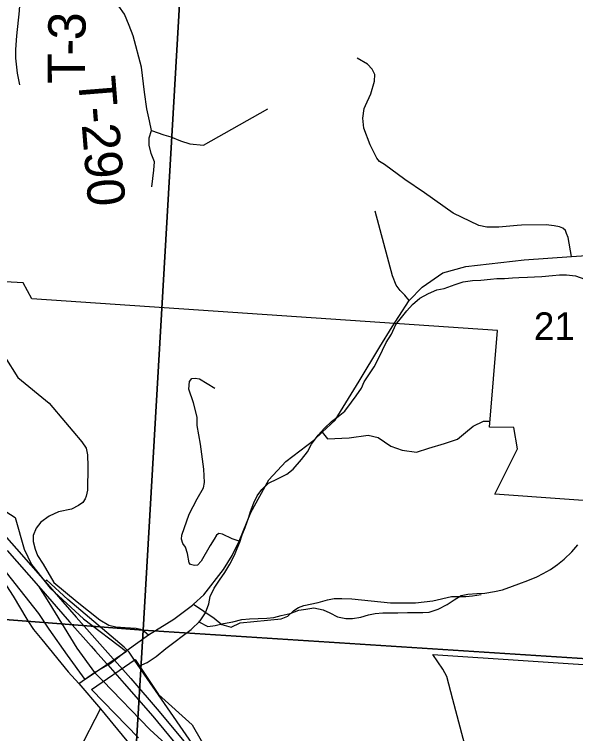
# Model space of a CAD drawing. Extents: x 0 to 34, y 0 to 22.
# Drawn here: x 3.35 to 4.203, y 15.269 to 16.363 of the extents above; entities that cross this region are included whole.
import ezdxf

# ---------------------------------------------------------------- set-up
doc = ezdxf.new("R2010")
doc.units = 0
for name, color, linetype in [('GM_X_City_Street', 7, 'Continuous'), ('GM_X_Corporation', 7, 'Continuous'), ('GM_X_Interchange_Ramps', 7, 'Continuous'), ('GM_X_Minor_River', 7, 'Continuous'), ('GM_X_Section_Text', 7, 'Continuous'), ('GM_X_State_Route', 7, 'Continuous'), ('GM_X_Township_Road', 7, 'Continuous'), ('GM_X_Township_Road_Text', 7, 'Continuous'), ('GM_X_US_Route', 7, 'Continuous')]:
    doc.layers.add(name, color=color, linetype=linetype)

msp = doc.modelspace()

# ---------------------------------------------------------------- linework, layer by layer
at = {"layer": 'GM_X_City_Street'}
for p, q in [((3.4478, 15.3456), (3.4715, 15.3624)), ((3.4355, 15.2191), (3.4806, 15.3072))]:
    msp.add_line(p, q, dxfattribs=at)
for points in [[(3.3351, 15.8422), (3.355, 15.8107), (3.4028, 15.7721), (3.4276, 15.7427), (3.4388, 15.7295)], [(3.6917, 15.5618), (3.6808, 15.5658), (3.6661, 15.5729), (3.6605, 15.5736), (3.657, 15.5709), (3.6534, 15.5649), (3.6476, 15.5556), (3.634, 15.5317), (3.6282, 15.5257), (3.6235, 15.5252), (3.6177, 15.5266), (3.6155, 15.5292), (3.6128, 15.5431), (3.6101, 15.5531), (3.6061, 15.5587), (3.6039, 15.5649), (3.6046, 15.5709), (3.6156, 15.6031), (3.6275, 15.6263), (3.6372, 15.6432), (3.639, 15.6513), (3.6377, 15.6716), (3.633, 15.7094), (3.6277, 15.7378), (3.6278, 15.7507), (3.6222, 15.7724), (3.6151, 15.7933), (3.6163, 15.8047), (3.6197, 15.8093), (3.6246, 15.81), (3.6311, 15.8088), (3.6545, 15.7947)], [(3.8178, 15.7276), (3.8261, 15.7176), (3.8587, 15.7194), (3.8876, 15.7234), (3.9027, 15.7195), (3.9224, 15.7065), (3.9394, 15.7004), (3.9614, 15.6973), (3.98, 15.7032), (4.0036, 15.7107), (4.0234, 15.7171), (4.0359, 15.7273), (4.0474, 15.7368), (4.0629, 15.7447), (4.0732, 15.7444)], [(3.4388, 15.7295), (3.4526, 15.7133), (3.4588, 15.7034), (3.4612, 15.6932), (3.4614, 15.6758), (3.4612, 15.6398), (3.4588, 15.6302), (3.4575, 15.6263), (3.4537, 15.6206), (3.4471, 15.6164), (3.4365, 15.6109), (3.417, 15.6065), (3.4028, 15.5998), (3.39, 15.5907), (3.383, 15.5816), (3.3786, 15.5708), (3.3783, 15.5617), (3.3813, 15.55), (3.3848, 15.5402), (3.3935, 15.5269), (3.4096, 15.4991), (3.4453, 15.4698), (3.4799, 15.4425), (3.4933, 15.4344), (3.5041, 15.4316), (3.5184, 15.4306), (3.5348, 15.4295), (3.5415, 15.4281), (3.547, 15.425), (3.554, 15.4194)], [(3.3114, 15.5339), (3.3479, 15.4786), (3.369, 15.4436)], [(3.622, 15.466), (3.6534, 15.4448), (3.6653, 15.4354), (3.6795, 15.4313), (3.6929, 15.4377), (3.7552, 15.444), (3.7654, 15.4481), (3.7746, 15.4565), (3.7817, 15.461), (3.7901, 15.4644), (3.8115, 15.4689), (3.8259, 15.4726), (3.8358, 15.4749), (3.8476, 15.4749), (3.863, 15.4741), (3.9215, 15.468), (3.9596, 15.468), (3.9862, 15.4714), (4.0142, 15.4778), (4.0361, 15.4781), (4.0461, 15.4789), (4.0594, 15.4807)], [(3.369, 15.4436), (3.3705, 15.4411), (3.3791, 15.4277), (3.3915, 15.4126), (3.4318, 15.3635), (3.4478, 15.3456)], [(3.4478, 15.3456), (3.4806, 15.3072), (3.5394, 15.2355), (3.5828, 15.1854), (3.5875, 15.1791), (3.6236, 15.1439), (3.6441, 15.1243), (3.6603, 15.1084), (3.6672, 15.0977), (3.6737, 15.0882), (3.7088, 15.0315), (3.776, 14.9293), (3.8503, 14.8112), (3.8974, 14.7371), (3.9444, 14.6625), (4.038, 14.514), (4.0485, 14.5009)]]:
    msp.add_lwpolyline(points, dxfattribs=at)
at = {"layer": 'GM_X_Corporation'}
for points in [[(3.6056, 16.4577), (3.5455, 15.4266), (2.5724, 15.5017), (2.6188, 16.52)], [(4.6087, 16.3871), (4.5353, 15.3628), (3.5455, 15.4266), (3.6056, 16.4577)], [(3.5455, 15.4266), (4.5353, 15.3628), (4.4813, 14.3453), (3.4851, 14.4189)]]:
    msp.add_lwpolyline(points, close=True, dxfattribs=at)
for points in [[(4.2921, 15.6181), (4.0804, 15.6335), (4.1149, 15.7024), (4.1093, 15.7347), (4.0722, 15.7353), (4.0842, 15.8825), (3.3765, 15.9305), (3.3633, 15.9548), (3.2992, 15.9585)], [(3.2977, 15.6319), (3.351, 15.5979), (3.3648, 15.55), (3.3757, 15.5264), (3.4044, 15.4906), (3.455, 15.4437), (3.5201, 15.3944), (3.4573, 15.3518), (3.4305, 15.3887), (3.4026, 15.4283), (3.3868, 15.4519), (3.3377, 15.5144)], [(2.6377, 15.2265), (2.6117, 15.2766), (2.597, 15.3031), (2.5781, 15.3392), (2.5705, 15.3517), (2.5668, 15.3574), (2.5528, 15.3783), (2.5294, 15.4116), (2.5203, 15.4333), (2.5199, 15.442), (2.5222, 15.4507), (2.5268, 15.4556), (2.5715, 15.4744), (2.5724, 15.5017), (3.5455, 15.4266), (3.4851, 14.4189)], [(4.0369, 15.2448), (4.0164, 15.3212), (4.0071, 15.3562), (4.001, 15.3676), (3.986, 15.3897), (4.2757, 15.3706)], [(3.5388, 15.2629), (3.4671, 15.3365), (3.5337, 15.3822), (3.5691, 15.3289), (3.6201, 15.2827), (3.6476, 15.2351)]]:
    msp.add_lwpolyline(points, dxfattribs=at)
at = {"layer": 'GM_X_Interchange_Ramps'}
for p, q in [((3.5518, 15.3532), (3.5327, 15.3809)), ((3.5691, 15.3282), (3.5518, 15.3532))]:
    msp.add_line(p, q, dxfattribs=at)
for points in [[(3.5214, 15.3965), (3.5169, 15.401), (3.4312, 15.4731), (3.3992, 15.5027), (3.3965, 15.5008)], [(3.5327, 15.3809), (3.5243, 15.393), (3.5214, 15.3965)], [(3.4715, 15.3624), (3.4759, 15.3583), (3.4842, 15.3497)], [(3.4842, 15.3497), (3.556, 15.2756), (3.6043, 15.231), (3.6211, 15.2145), (3.625, 15.2177)], [(3.6275, 15.2334), (3.6321, 15.2365), (3.6247, 15.2478), (3.5691, 15.3282)]]:
    msp.add_lwpolyline(points, dxfattribs=at)
at = {"layer": 'GM_X_Minor_River'}
for points in [[(3.539, 15.3721), (3.5519, 15.3777), (3.5655, 15.3869), (3.5803, 15.399), (3.5942, 15.4096), (3.6048, 15.4176), (3.6188, 15.4275), (3.6324, 15.4407), (3.6404, 15.4529), (3.6453, 15.4665), (3.6476, 15.4779), (3.6536, 15.4904), (3.6615, 15.5026), (3.6699, 15.5143), (3.6774, 15.5272), (3.6846, 15.5405), (3.6888, 15.5507), (3.6926, 15.5606), (3.6963, 15.5716), (3.7009, 15.583), (3.7058, 15.597), (3.7088, 15.6069), (3.7137, 15.6205), (3.719, 15.6311), (3.7262, 15.6406), (3.7364, 15.6501), (3.75, 15.6569), (3.764, 15.6638), (3.7738, 15.6717), (3.7863, 15.6861), (3.7954, 15.6979), (3.8015, 15.7097), (3.8117, 15.7233), (3.8211, 15.7339), (3.8321, 15.7438), (3.8423, 15.7514), (3.8521, 15.7597), (3.8623, 15.7734), (3.8695, 15.7829), (3.8774, 15.7946), (3.8816, 15.8045), (3.8888, 15.8147), (3.8967, 15.8269), (3.9032, 15.8398), (3.9096, 15.8523), (3.9153, 15.8641), (3.9232, 15.8766), (3.93, 15.8914), (3.9383, 15.902), (3.9466, 15.9122), (3.9553, 15.9217), (3.9663, 15.9316), (3.9792, 15.9384), (3.992, 15.9441), (4.0034, 15.9464), (4.02, 15.9525), (4.0321, 15.9563), (4.0464, 15.9582), (4.0589, 15.9589), (4.0737, 15.9604), (4.0835, 15.9612), (4.0952, 15.9616), (4.1069, 15.9624), (4.1168, 15.9627), (4.13, 15.9635), (4.1406, 15.9639), (4.1519, 15.9647), (4.1678, 15.9658), (4.1787, 15.9669), (4.1893, 15.9669), (4.2029, 15.9654), (4.2169, 15.9605)], [(3.6324, 15.4407), (3.6302, 15.4396), (3.6438, 15.4324), (3.6551, 15.4339), (3.668, 15.4366), (3.6819, 15.4396), (3.6959, 15.443), (3.7073, 15.4438), (3.7205, 15.4446), (3.7337, 15.4449), (3.7443, 15.4461), (3.7557, 15.4488), (3.7689, 15.4522), (3.7825, 15.4571), (3.7931, 15.4586), (3.8052, 15.4605), (3.8195, 15.4575), (3.8294, 15.4533), (3.8411, 15.4469), (3.8536, 15.4442), (3.8638, 15.4443), (3.8766, 15.4465), (3.8883, 15.45), (3.8985, 15.4522), (3.9099, 15.453), (3.9326, 15.453), (3.9473, 15.4534), (3.959, 15.4538), (3.9707, 15.4534), (3.9806, 15.4542), (3.9942, 15.4587), (4.0078, 15.4659), (4.0184, 15.4728), (4.0293, 15.4792), (4.0392, 15.4815), (4.0531, 15.4826), (4.0652, 15.483), (4.08, 15.4853), (4.0917, 15.488), (4.1072, 15.4937), (4.117, 15.4971), (4.1306, 15.502), (4.1439, 15.5077), (4.1537, 15.513), (4.165, 15.5187), (4.1753, 15.5267), (4.1858, 15.5346), (4.1972, 15.5457), (4.2063, 15.5567)]]:
    msp.add_lwpolyline(points, dxfattribs=at)
at = {"layer": 'GM_X_State_Route'}
msp.add_line((3.9342, 15.9036), (3.9501, 15.9279), dxfattribs=at)
for points in [[(3.9501, 15.9279), (3.9698, 15.9484), (4.0012, 15.9699), (4.0362, 15.9799), (4.1249, 15.9899), (4.1968, 15.9947), (4.2431, 15.9978)], [(3.6204, 15.4648), (3.622, 15.466), (3.6381, 15.4802), (3.6679, 15.519), (3.681, 15.5402), (3.6917, 15.5618), (3.7094, 15.6057), (3.7367, 15.6553), (3.7625, 15.6833), (3.8051, 15.7156), (3.8178, 15.7276), (3.8374, 15.7462), (3.8739, 15.8055), (3.9055, 15.8575), (3.9241, 15.8881), (3.9342, 15.9036)], [(3.3864, 15.4935), (3.4022, 15.4686), (3.4446, 15.3992), (3.4715, 15.3624)], [(3.5214, 15.3965), (3.554, 15.4194), (3.5924, 15.4435), (3.6204, 15.4648)], [(3.4715, 15.3624), (3.4917, 15.374), (3.4971, 15.3771), (3.502, 15.381), (3.5214, 15.3965)]]:
    msp.add_lwpolyline(points, dxfattribs=at)
at = {"layer": 'GM_X_Township_Road'}
for points in [[(3.3583, 16.256), (3.3548, 16.2736), (3.3519, 16.2967), (3.3519, 16.3094), (3.3535, 16.3304), (3.3579, 16.3684), (3.3591, 16.3951), (3.3633, 16.4164), (3.3662, 16.4412), (3.3704, 16.4526)], [(3.559, 16.1007), (3.5619, 16.1263), (3.5631, 16.1387), (3.5578, 16.1514), (3.5547, 16.1643), (3.5549, 16.1755), (3.5583, 16.1865), (3.5554, 16.2011), (3.5513, 16.2195), (3.5479, 16.2447), (3.543, 16.283), (3.5306, 16.3306), (3.5245, 16.3463), (3.5172, 16.3632), (3.5088, 16.3755), (3.498, 16.3868), (3.4873, 16.3956), (3.4826, 16.401), (3.477, 16.4142), (3.4702, 16.4295), (3.4638, 16.4377), (3.454, 16.4468)], [(3.8836, 16.2243), (3.8916, 16.2423), (3.8973, 16.2616), (3.8979, 16.2714), (3.8939, 16.2795), (3.8868, 16.2872), (3.8711, 16.2963)], [(3.5583, 16.1865), (3.5769, 16.18), (3.5877, 16.1767), (3.6025, 16.1707), (3.6166, 16.1664), (3.6374, 16.164), (3.7351, 16.2192)], [(3.9731, 16.0915), (3.9437, 16.1121), (3.9127, 16.1348), (3.9049, 16.1392), (3.9008, 16.1442), (3.891, 16.1645), (3.8809, 16.1898), (3.8794, 16.2054), (3.8816, 16.2198), (3.8836, 16.2243)], [(4.114, 16.0418), (4.0865, 16.0397), (4.0679, 16.0397), (4.0558, 16.0418), (4.0168, 16.0609), (3.9731, 16.0915)], [(3.9501, 15.9279), (3.9433, 15.936), (3.9366, 15.943), (3.9303, 15.9515), (3.9246, 15.9656), (3.8983, 16.0638)], [(4.1968, 15.9947), (4.1919, 16.0238), (4.1893, 16.0299), (4.1875, 16.0345), (4.1838, 16.038), (4.1786, 16.04), (4.1703, 16.0413), (4.1582, 16.0431), (4.1206, 16.0424), (4.114, 16.0418)]]:
    msp.add_lwpolyline(points, dxfattribs=at)
at = {"layer": 'GM_X_US_Route'}
msp.add_line((3.4665, 15.4023), (3.4732, 15.3948), dxfattribs=at)
for points in [[(3.3186, 15.5889), (3.353, 15.5504), (3.3965, 15.5008), (3.4439, 15.4465), (3.5, 15.3833), (3.502, 15.381), (3.5268, 15.3531), (3.5702, 15.3031), (3.6275, 15.2334)], [(3.3389, 15.5477), (3.3864, 15.4935), (3.4338, 15.4392), (3.4665, 15.4023)], [(3.4732, 15.3948), (3.4899, 15.376), (3.4917, 15.374), (3.5167, 15.3457), (3.5601, 15.2957), (3.6178, 15.2267)]]:
    msp.add_lwpolyline(points, dxfattribs=at)

# ---------------------------------------------------------------- texts
at = {"layer": 'GM_X_Section_Text'}
msp.add_text('21', height=0.04186, rotation=0, dxfattribs=at).set_placement((4.1397, 15.8681))
at = {"layer": 'GM_X_Township_Road_Text'}
for s, height, rotation, p in [('3', 0.0568, 87.7096, (3.4573, 16.3232)), ('-', 0.0568, 89.6643, (3.4572, 16.3004)), ('T', 0.0568, 90.3514, (3.4574, 16.258)), ('T-290', 0.05682, 274.6514, (3.4464, 16.267))]:
    msp.add_text(s, height=height, rotation=rotation, dxfattribs=at).set_placement(p)

doc.saveas('drawing.dxf')
